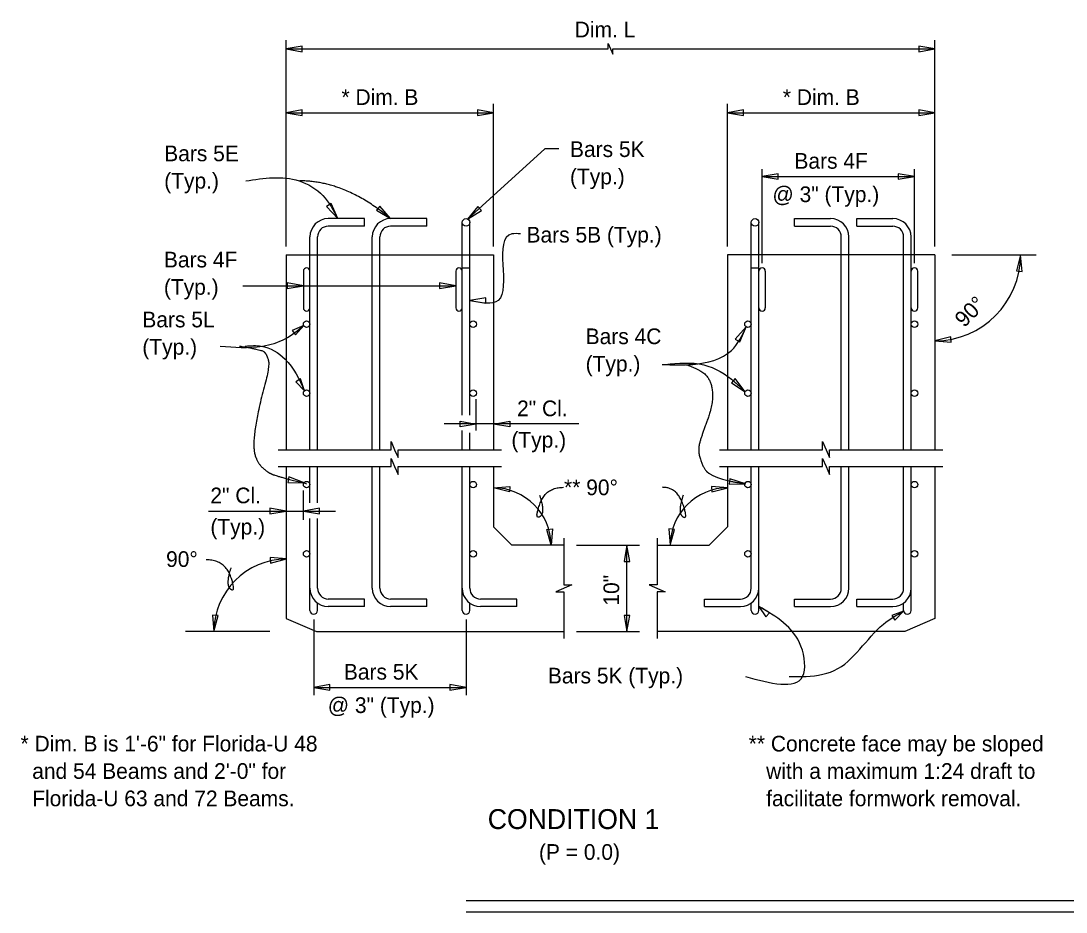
# Model space of a CAD drawing. Extents: x 120790.7 to 120844.8, y 120612.1 to 120653.6.
# Drawn here: x 120791.21 to 120801.28, y 120612.48 to 120621.08 of the extents above; entities that cross this region are included whole.
import ezdxf

# ---------------------------------------------------------------- set-up
doc = ezdxf.new("R2010")
doc.units = 0
for name, color, linetype in [('AdhocPoint_dp', 7, 'Continuous'), ('Patterning', 7, 'Continuous'), ('PlotBorder_dp', 7, 'Continuous'), ('SheetBorder_dp', 7, 'Continuous')]:
    doc.layers.add(name, color=color, linetype=linetype)

# ---------------------------------------------------------------- blocks, each defined once
blk = doc.blocks.new('Terminator-Arrow')
at = {"layer": 'PlotBorder_dp'}
blk.add_lwpolyline([(0, 0), (-0.00041, 0.000069), (-0.00041, -0.000069)], close=True, dxfattribs=at)

msp = doc.modelspace()

# ---------------------------------------------------------------- linework, layer by layer
at = {"layer": 'AdhocPoint_dp'}
for p, q in [((120793.762, 120618.823), (120795.762, 120618.823)), ((120793.762, 120618.823), (120793.762, 120616.945)), ((120795.762, 120618.823), (120795.762, 120616.945)), ((120800.017, 120618.823), (120798.017, 120618.823)), ((120798.017, 120618.823), (120798.017, 120616.945)), ((120800.017, 120618.823), (120800.017, 120616.945)), ((120793.762, 120616.783), (120793.762, 120615.316)), ((120795.762, 120616.783), (120795.762, 120616.201)), ((120798.017, 120616.783), (120798.017, 120616.201)), ((120800.017, 120616.783), (120800.017, 120615.316)), ((120795.939, 120616.024), (120795.762, 120616.201)), ((120797.841, 120616.024), (120798.017, 120616.201)), ((120796.44, 120616.024), (120795.939, 120616.024)), ((120797.34, 120616.024), (120797.841, 120616.024)), ((120793.762, 120615.316), (120794.054, 120615.191)), ((120800.017, 120615.316), (120799.726, 120615.191)), ((120794.054, 120615.191), (120796.44, 120615.191)), ((120799.726, 120615.191), (120797.34, 120615.191))]:
    msp.add_line(p, q, dxfattribs=at)
at = {"layer": 'PlotBorder_dp'}
for p, q in [((120793.762, 120618.906), (120793.762, 120620.896)), ((120793.762, 120618.906), (120793.762, 120620.896)), ((120800.017, 120618.906), (120800.017, 120620.896)), ((120800.017, 120618.906), (120800.017, 120620.896)), ((120793.762, 120620.195), (120795.762, 120620.195)), ((120793.762, 120620.195), (120795.762, 120620.195)), ((120795.762, 120618.906), (120795.762, 120620.28)), ((120795.762, 120618.906), (120795.762, 120620.28)), ((120798.017, 120618.906), (120798.017, 120620.28)), ((120798.017, 120618.906), (120798.017, 120620.28)), ((120798.017, 120620.195), (120800.017, 120620.195)), ((120798.017, 120620.195), (120800.017, 120620.195)), ((120798.351, 120618.744), (120798.351, 120619.651)), ((120798.351, 120618.744), (120798.351, 120619.651)), ((120798.351, 120619.58), (120799.82, 120619.58)), ((120798.351, 120619.58), (120799.82, 120619.58)), ((120799.82, 120618.744), (120799.82, 120619.651)), ((120799.82, 120618.744), (120799.82, 120619.651)), ((120800.18, 120618.823), (120800.994, 120618.823)), ((120800.18, 120618.823), (120800.994, 120618.823)), ((120793.344, 120618.527), (120793.929, 120618.527)), ((120793.344, 120618.527), (120793.929, 120618.527)), ((120793.929, 120618.527), (120795.398, 120618.527)), ((120793.929, 120618.527), (120795.398, 120618.527)), ((120795.596, 120617.13), (120795.596, 120617.431)), ((120795.596, 120617.13), (120795.596, 120617.431)), ((120796.585, 120617.193), (120795.286, 120617.193)), ((120796.585, 120617.193), (120795.286, 120617.193)), ((120793.929, 120616.268), (120793.929, 120616.551)), ((120793.929, 120616.268), (120793.929, 120616.551)), ((120793.013, 120616.353), (120794.239, 120616.353)), ((120793.013, 120616.353), (120794.239, 120616.353)), ((120796.561, 120616.024), (120797.169, 120616.024)), ((120796.561, 120616.024), (120797.169, 120616.024)), ((120797.048, 120615.191), (120797.048, 120616.024)), ((120797.048, 120615.191), (120797.048, 120616.024)), ((120794.028, 120615.308), (120794.028, 120614.577)), ((120794.028, 120615.308), (120794.028, 120614.577)), ((120795.497, 120615.308), (120795.497, 120614.577)), ((120795.497, 120615.308), (120795.497, 120614.577)), ((120793.605, 120615.191), (120792.791, 120615.191)), ((120793.605, 120615.191), (120792.791, 120615.191)), ((120796.561, 120615.191), (120797.169, 120615.191)), ((120796.561, 120615.191), (120797.169, 120615.191)), ((120794.028, 120614.652), (120795.497, 120614.652)), ((120794.028, 120614.652), (120795.497, 120614.652)), ((120802.747, 120612.593), (120795.497, 120612.593)), ((120802.747, 120612.593), (120795.497, 120612.593)), ((120802.747, 120612.485), (120795.497, 120612.485)), ((120802.747, 120612.485), (120795.497, 120612.485))]:
    msp.add_line(p, q, dxfattribs=at)
for points in [[(120793.762, 120620.81), (120796.867, 120620.81), (120796.867, 120620.862), (120796.89, 120620.81), (120796.912, 120620.759), (120796.912, 120620.81), (120800.017, 120620.81)], [(120793.762, 120620.81), (120796.867, 120620.81), (120796.867, 120620.862), (120796.89, 120620.81), (120796.912, 120620.759), (120796.912, 120620.81), (120800.017, 120620.81)], [(120796.39, 120619.846), (120796.257, 120619.846), (120795.512, 120619.167)], [(120796.39, 120619.846), (120796.257, 120619.846), (120795.512, 120619.167)], [(120793.687, 120616.945), (120794.775, 120616.945), (120794.775, 120617.023), (120794.808, 120616.945), (120794.842, 120616.868), (120794.842, 120616.945), (120795.838, 120616.945)], [(120793.687, 120616.945), (120794.775, 120616.945), (120794.775, 120617.023), (120794.808, 120616.945), (120794.842, 120616.868), (120794.842, 120616.945), (120795.838, 120616.945)], [(120797.942, 120616.945), (120798.935, 120616.945), (120798.935, 120617.023), (120798.968, 120616.945), (120799.002, 120616.868), (120799.002, 120616.945), (120800.093, 120616.945)], [(120797.942, 120616.945), (120798.935, 120616.945), (120798.935, 120617.023), (120798.968, 120616.945), (120799.002, 120616.868), (120799.002, 120616.945), (120800.093, 120616.945)], [(120793.687, 120616.783), (120794.775, 120616.783), (120794.775, 120616.861), (120794.808, 120616.783), (120794.842, 120616.706), (120794.842, 120616.783), (120795.838, 120616.783)], [(120793.687, 120616.783), (120794.775, 120616.783), (120794.775, 120616.861), (120794.808, 120616.783), (120794.842, 120616.706), (120794.842, 120616.783), (120795.838, 120616.783)], [(120797.942, 120616.783), (120798.935, 120616.783), (120798.935, 120616.861), (120798.968, 120616.783), (120799.002, 120616.706), (120799.002, 120616.783), (120800.093, 120616.783)], [(120797.942, 120616.783), (120798.935, 120616.783), (120798.935, 120616.861), (120798.968, 120616.783), (120799.002, 120616.706), (120799.002, 120616.783), (120800.093, 120616.783)], [(120796.44, 120616.092), (120796.44, 120615.642), (120796.517, 120615.642), (120796.362, 120615.574), (120796.44, 120615.574), (120796.44, 120615.124)], [(120796.44, 120616.092), (120796.44, 120615.642), (120796.517, 120615.642), (120796.362, 120615.574), (120796.44, 120615.574), (120796.44, 120615.124)], [(120797.34, 120616.092), (120797.34, 120615.642), (120797.263, 120615.642), (120797.418, 120615.574), (120797.34, 120615.574), (120797.34, 120615.124)], [(120797.34, 120616.092), (120797.34, 120615.642), (120797.263, 120615.642), (120797.418, 120615.574), (120797.34, 120615.574), (120797.34, 120615.124)]]:
    msp.add_lwpolyline(points, dxfattribs=at)
for points in [[(120794.26, 120619.174), (120794.198, 120619.32), (120794.153, 120619.291)], [(120794.26, 120619.174), (120794.198, 120619.32), (120794.153, 120619.291)], [(120794.77, 120619.174), (120794.667, 120619.295), (120794.633, 120619.254)], [(120794.77, 120619.174), (120794.667, 120619.295), (120794.633, 120619.254)], [(120795.512, 120619.167), (120795.645, 120619.253), (120795.61, 120619.292)], [(120795.512, 120619.167), (120795.645, 120619.253), (120795.61, 120619.292)], [(120800.843, 120618.823), (120800.805, 120618.669), (120800.857, 120618.665)], [(120800.843, 120618.823), (120800.805, 120618.669), (120800.857, 120618.665)], [(120793.929, 120618.527), (120793.773, 120618.553), (120793.773, 120618.5)], [(120793.929, 120618.527), (120793.773, 120618.553), (120793.773, 120618.5)], [(120795.398, 120618.527), (120795.242, 120618.553), (120795.242, 120618.5)], [(120795.398, 120618.527), (120795.242, 120618.553), (120795.242, 120618.5)], [(120795.533, 120618.384), (120795.689, 120618.357), (120795.689, 120618.41)], [(120795.533, 120618.384), (120795.689, 120618.357), (120795.689, 120618.41)], [(120793.932, 120618.143), (120793.822, 120618.096), (120793.852, 120618.053)], [(120793.932, 120618.143), (120793.822, 120618.096), (120793.852, 120618.053)], [(120798.199, 120618.13), (120798.093, 120618.012), (120798.138, 120617.984)], [(120798.199, 120618.13), (120798.093, 120618.012), (120798.138, 120617.984)], [(120800.017, 120617.995), (120800.175, 120617.982), (120800.171, 120618.035)], [(120800.017, 120617.995), (120800.175, 120617.982), (120800.171, 120618.035)], [(120793.941, 120617.514), (120793.902, 120617.628), (120793.857, 120617.6)], [(120793.941, 120617.514), (120793.902, 120617.628), (120793.857, 120617.6)], [(120798.187, 120617.503), (120798.092, 120617.63), (120798.056, 120617.591)], [(120798.187, 120617.503), (120798.092, 120617.63), (120798.056, 120617.591)], [(120793.937, 120616.624), (120793.79, 120616.682), (120793.779, 120616.63)], [(120793.937, 120616.624), (120793.79, 120616.682), (120793.779, 120616.63)], [(120798.191, 120616.617), (120798.04, 120616.664), (120798.033, 120616.612)], [(120798.191, 120616.617), (120798.04, 120616.664), (120798.033, 120616.612)], [(120795.762, 120616.578), (120795.92, 120616.591), (120795.916, 120616.538)], [(120795.762, 120616.578), (120795.92, 120616.591), (120795.916, 120616.538)], [(120798.02, 120616.578), (120797.862, 120616.591), (120797.866, 120616.538)], [(120798.02, 120616.578), (120797.862, 120616.591), (120797.866, 120616.538)], [(120796.317, 120616.023), (120796.276, 120616.175), (120796.329, 120616.181)], [(120796.317, 120616.023), (120796.276, 120616.175), (120796.329, 120616.181)], [(120797.465, 120616.023), (120797.506, 120616.175), (120797.453, 120616.181)], [(120797.465, 120616.023), (120797.506, 120616.175), (120797.453, 120616.181)], [(120797.048, 120616.024), (120797.022, 120615.868), (120797.075, 120615.868)], [(120797.048, 120616.024), (120797.022, 120615.868), (120797.075, 120615.868)], [(120793.765, 120615.891), (120793.607, 120615.904), (120793.611, 120615.851)], [(120793.765, 120615.891), (120793.607, 120615.904), (120793.611, 120615.851)], [(120793.065, 120615.191), (120793.106, 120615.344), (120793.054, 120615.349)], [(120793.065, 120615.191), (120793.106, 120615.344), (120793.054, 120615.349)], [(120797.048, 120615.191), (120797.075, 120615.347), (120797.022, 120615.347)], [(120797.048, 120615.191), (120797.075, 120615.347), (120797.022, 120615.347)], [(120798.32, 120615.434), (120798.386, 120615.334), (120798.423, 120615.372)], [(120798.32, 120615.434), (120798.386, 120615.334), (120798.423, 120615.372)], [(120799.716, 120615.388), (120799.603, 120615.346), (120799.632, 120615.302)], [(120799.716, 120615.388), (120799.603, 120615.346), (120799.632, 120615.302)]]:
    msp.add_lwpolyline(points, close=True, dxfattribs=at)
for centre, radius, start, end in [((120800.015, 120618.823), 0.828, 270.1769, 0), ((120800.015, 120618.823), 0.828, 270.1769, 0), ((120795.758, 120616.019), 0.559, 0.3991, 89.55), ((120795.758, 120616.019), 0.559, 0.3991, 89.55), ((120798.024, 120616.019), 0.559, 90.45, 179.6009), ((120798.024, 120616.019), 0.559, 90.45, 179.6009), ((120793.77, 120615.186), 0.705, 90.45, 179.6009), ((120793.77, 120615.186), 0.705, 90.45, 179.6009)]:
    msp.add_arc(centre, radius, start, end, dxfattribs=at)
for points in [[(120793.373, 120619.538), (120793.887, 120619.538), (120794.117, 120619.396), (120794.26, 120619.174)], [(120793.373, 120619.538), (120793.887, 120619.538), (120794.117, 120619.396), (120794.26, 120619.174)], [(120796.023, 120619.026), (120795.939, 120619.026), (120795.807, 120618.384), (120795.533, 120618.384)], [(120796.023, 120619.026), (120795.939, 120619.026), (120795.807, 120618.384), (120795.533, 120618.384)], [(120793.125, 120617.944), (120793.534, 120617.944), (120793.753, 120618.015), (120793.932, 120618.143)], [(120793.125, 120617.944), (120793.534, 120617.944), (120793.753, 120618.015), (120793.932, 120618.143)], [(120797.389, 120617.768), (120797.683, 120617.768), (120798.056, 120617.902), (120798.199, 120618.13)], [(120797.389, 120617.768), (120797.683, 120617.768), (120798.056, 120617.902), (120798.199, 120618.13)], [(120793.369, 120617.944), (120793.523, 120617.944), (120793.753, 120617.818), (120793.941, 120617.514)], [(120793.369, 120617.944), (120793.523, 120617.944), (120793.753, 120617.818), (120793.941, 120617.514)], [(120797.417, 120617.768), (120797.788, 120617.763), (120798.089, 120617.597), (120798.187, 120617.503)], [(120797.417, 120617.768), (120797.788, 120617.763), (120798.089, 120617.597), (120798.187, 120617.503)], [(120798.19, 120614.757), (120798.741, 120614.757), (120798.726, 120615.049), (120798.32, 120615.434)], [(120798.19, 120614.757), (120798.741, 120614.757), (120798.726, 120615.049), (120798.32, 120615.434)], [(120798.611, 120614.757), (120798.735, 120614.757), (120799.047, 120614.815), (120799.522, 120615.262), (120799.716, 120615.388)], [(120798.611, 120614.757), (120798.735, 120614.757), (120799.047, 120614.815), (120799.522, 120615.262), (120799.716, 120615.388)]]:
    msp.add_spline(points, degree=3, dxfattribs=at)
for points in [[(120794.77, 120619.174), (120794.332, 120619.538), (120793.895, 120619.538)], [(120794.77, 120619.174), (120794.332, 120619.538), (120793.895, 120619.538)], [(120793.313, 120617.944), (120793.528, 120617.911), (120793.574, 120617.865), (120793.608, 120617.753), (120793.49, 120617.328), (120793.438, 120616.966), (120793.49, 120616.811), (120793.593, 120616.718), (120793.707, 120616.681), (120793.958, 120616.617)], [(120793.313, 120617.944), (120793.528, 120617.911), (120793.574, 120617.865), (120793.608, 120617.753), (120793.49, 120617.328), (120793.438, 120616.966), (120793.49, 120616.811), (120793.593, 120616.718), (120793.707, 120616.681), (120793.958, 120616.617)], [(120797.617, 120617.765), (120797.783, 120617.712), (120797.874, 120617.569), (120797.874, 120617.365), (120797.778, 120617.108), (120797.726, 120616.937), (120797.788, 120616.761), (120797.85, 120616.704), (120798.011, 120616.642), (120798.191, 120616.617)], [(120797.617, 120617.765), (120797.783, 120617.712), (120797.874, 120617.569), (120797.874, 120617.365), (120797.778, 120617.108), (120797.726, 120616.937), (120797.788, 120616.761), (120797.85, 120616.704), (120798.011, 120616.642), (120798.191, 120616.617)], [(120796.206, 120616.505), (120796.264, 120616.333), (120796.153, 120616.264), (120796.265, 120616.582), (120796.437, 120616.582)], [(120796.206, 120616.505), (120796.264, 120616.333), (120796.153, 120616.264), (120796.265, 120616.582), (120796.437, 120616.582)], [(120797.59, 120616.505), (120797.532, 120616.333), (120797.643, 120616.264), (120797.53, 120616.582), (120797.391, 120616.582)], [(120797.59, 120616.505), (120797.532, 120616.333), (120797.643, 120616.264), (120797.53, 120616.582), (120797.391, 120616.582)], [(120793.23, 120615.806), (120793.173, 120615.634), (120793.284, 120615.565), (120793.171, 120615.882), (120792.993, 120615.882)], [(120793.23, 120615.806), (120793.173, 120615.634), (120793.284, 120615.565), (120793.171, 120615.882), (120792.993, 120615.882)]]:
    msp.add_open_spline(points, degree=2, dxfattribs=at)
at = {"layer": 'SheetBorder_dp'}
for p, q in [((120794.517, 120619.174), (120794.169, 120619.174)), ((120794.517, 120619.101), (120794.169, 120619.101)), ((120794.517, 120619.101), (120794.517, 120619.174)), ((120795.118, 120619.174), (120794.77, 120619.174)), ((120795.118, 120619.101), (120794.77, 120619.101)), ((120795.118, 120619.101), (120795.118, 120619.174)), ((120795.46, 120617.278), (120795.46, 120619.137)), ((120795.533, 120617.278), (120795.533, 120619.137)), ((120798.247, 120616.945), (120798.247, 120619.137)), ((120798.32, 120616.945), (120798.32, 120619.137)), ((120798.663, 120619.174), (120799.011, 120619.174)), ((120798.663, 120619.101), (120798.663, 120619.174)), ((120798.663, 120619.101), (120799.011, 120619.101)), ((120799.263, 120619.174), (120799.611, 120619.174)), ((120799.263, 120619.101), (120799.263, 120619.174)), ((120799.263, 120619.101), (120799.611, 120619.101)), ((120793.992, 120616.945), (120793.992, 120618.997)), ((120794.065, 120616.945), (120794.065, 120618.997)), ((120794.593, 120616.945), (120794.593, 120618.997)), ((120794.665, 120616.945), (120794.665, 120618.997)), ((120799.115, 120616.945), (120799.115, 120618.997)), ((120799.188, 120616.945), (120799.188, 120618.997)), ((120799.715, 120616.945), (120799.715, 120618.997)), ((120799.788, 120616.945), (120799.788, 120618.997)), ((120795.46, 120618.698), (120795.533, 120618.698)), ((120798.247, 120618.698), (120798.32, 120618.698)), ((120793.929, 120618.667), (120793.929, 120618.313)), ((120795.398, 120618.667), (120795.398, 120618.313)), ((120798.382, 120618.667), (120798.382, 120618.313)), ((120799.851, 120618.667), (120799.851, 120618.313)), ((120795.46, 120616.945), (120795.46, 120617.131)), ((120795.533, 120616.945), (120795.533, 120617.109)), ((120793.992, 120616.432), (120793.992, 120616.783)), ((120794.065, 120616.432), (120794.065, 120616.783)), ((120794.593, 120615.608), (120794.593, 120616.783)), ((120794.665, 120615.608), (120794.665, 120616.783)), ((120795.46, 120615.394), (120795.46, 120616.783)), ((120795.533, 120615.608), (120795.533, 120616.783)), ((120798.247, 120615.608), (120798.247, 120616.783)), ((120798.32, 120615.394), (120798.32, 120616.783)), ((120799.115, 120615.608), (120799.115, 120616.783)), ((120799.188, 120615.608), (120799.188, 120616.783)), ((120799.715, 120615.608), (120799.715, 120616.783)), ((120799.788, 120615.394), (120799.788, 120616.783)), ((120793.992, 120615.394), (120793.992, 120616.28)), ((120794.065, 120615.608), (120794.065, 120616.28)), ((120794.065, 120615.394), (120794.065, 120615.465)), ((120794.517, 120615.504), (120794.169, 120615.504)), ((120794.517, 120615.431), (120794.517, 120615.504)), ((120795.118, 120615.504), (120794.77, 120615.504)), ((120795.118, 120615.431), (120795.118, 120615.504)), ((120795.533, 120615.394), (120795.533, 120615.465)), ((120795.985, 120615.504), (120795.637, 120615.504)), ((120795.985, 120615.431), (120795.985, 120615.504)), ((120797.795, 120615.504), (120798.142, 120615.504)), ((120797.795, 120615.431), (120797.795, 120615.504)), ((120798.247, 120615.394), (120798.247, 120615.465)), ((120798.663, 120615.504), (120799.011, 120615.504)), ((120798.663, 120615.431), (120798.663, 120615.504)), ((120799.263, 120615.504), (120799.611, 120615.504)), ((120799.263, 120615.431), (120799.263, 120615.504)), ((120799.715, 120615.394), (120799.715, 120615.465)), ((120794.517, 120615.431), (120794.169, 120615.431)), ((120795.118, 120615.431), (120794.77, 120615.431)), ((120795.985, 120615.431), (120795.637, 120615.431)), ((120797.795, 120615.431), (120798.142, 120615.431)), ((120798.663, 120615.431), (120799.011, 120615.431)), ((120799.263, 120615.431), (120799.611, 120615.431))]:
    msp.add_line(p, q, dxfattribs=at)
for centre, radius in [((120795.497, 120619.137), 0.0365), ((120798.283, 120619.137), 0.0365), ((120793.96, 120618.156), 0.0312), ((120795.565, 120618.156), 0.0312), ((120798.215, 120618.156), 0.0312), ((120799.82, 120618.156), 0.0312), ((120793.96, 120617.49), 0.0312), ((120795.565, 120617.49), 0.0312), ((120798.215, 120617.49), 0.0312), ((120799.82, 120617.49), 0.0312), ((120793.96, 120616.608), 0.0312), ((120795.565, 120616.608), 0.0312), ((120798.215, 120616.608), 0.0312), ((120799.82, 120616.608), 0.0312), ((120793.96, 120615.941), 0.0312), ((120795.565, 120615.941), 0.0312), ((120798.215, 120615.941), 0.0312), ((120799.82, 120615.941), 0.0312)]:
    msp.add_circle(centre, radius, dxfattribs=at)
for centre, radius, start, end in [((120794.169, 120618.997), 0.177, 90, 180), ((120794.169, 120618.997), 0.104, 90, 180), ((120794.77, 120618.997), 0.177, 90, 180), ((120794.77, 120618.997), 0.104, 90, 180), ((120799.011, 120618.997), 0.177, 0, 90), ((120799.011, 120618.997), 0.104, 0, 90), ((120799.611, 120618.997), 0.177, 0, 90), ((120799.611, 120618.997), 0.104, 0, 90), ((120793.96, 120618.667), 0.0312, 0, 180), ((120795.429, 120618.667), 0.0312, 0, 180), ((120798.351, 120618.667), 0.0312, 0, 180), ((120799.82, 120618.667), 0.0312, 0, 180), ((120793.96, 120618.313), 0.0312, 180, 0), ((120795.429, 120618.313), 0.0312, 180, 0), ((120798.351, 120618.313), 0.0312, 180, 0), ((120799.82, 120618.313), 0.0312, 180, 0), ((120794.169, 120615.608), 0.177, 180, 270), ((120794.169, 120615.608), 0.104, 180, 270), ((120794.77, 120615.608), 0.177, 180, 270), ((120794.77, 120615.608), 0.104, 180, 270), ((120795.637, 120615.608), 0.177, 180, 270), ((120795.637, 120615.608), 0.104, 180, 270), ((120798.142, 120615.608), 0.104, 270, 360), ((120798.142, 120615.608), 0.177, 270, 360), ((120799.011, 120615.608), 0.104, 270, 0), ((120799.011, 120615.608), 0.177, 270, 0), ((120799.611, 120615.608), 0.104, 270, 360), ((120799.611, 120615.608), 0.177, 270, 360), ((120794.028, 120615.394), 0.0365, 180, 0), ((120795.497, 120615.394), 0.0365, 180, 0), ((120798.283, 120615.394), 0.0365, 180, 0), ((120799.752, 120615.394), 0.0365, 180, 0)]:
    msp.add_arc(centre, radius, start, end, dxfattribs=at)

# ---------------------------------------------------------------- block references
at = {"layer": 'PlotBorder_dp', "xscale": 381, "rotation": 180}
for p, yscale in [((120793.762, 120620.81), 384.0238095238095), ((120793.762, 120620.81), 384.0238095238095), ((120793.762, 120620.195), 384.0238095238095), ((120793.762, 120620.195), 384.0238095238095), ((120798.017, 120620.195), 384.0238095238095), ((120798.017, 120620.195), 384.0238095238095), ((120798.351, 120619.58), 384.0238095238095), ((120798.351, 120619.58), 384.0238095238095), ((120795.762, 120617.192), -384.0238095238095), ((120795.762, 120617.192), -384.0238095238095), ((120793.929, 120616.353), 384.0238095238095), ((120793.929, 120616.353), 384.0238095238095), ((120794.028, 120614.652), 384.0238095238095), ((120794.028, 120614.652), 384.0238095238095)]:
    msp.add_blockref('Terminator-Arrow', p, dxfattribs=dict(at, yscale=yscale))
at = {"layer": 'PlotBorder_dp', "xscale": 381}
for p, yscale in [((120800.017, 120620.81), 384.0238095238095), ((120800.017, 120620.81), 384.0238095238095), ((120795.762, 120620.195), 384.0238095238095), ((120795.762, 120620.195), 384.0238095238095), ((120800.017, 120620.195), 384.0238095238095), ((120800.017, 120620.195), 384.0238095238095), ((120799.819, 120619.58), 384.0238095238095), ((120799.819, 120619.58), 384.0238095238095), ((120795.596, 120617.192), -384.0238095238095), ((120795.596, 120617.192), -384.0238095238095), ((120793.762, 120616.353), 384.0238095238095), ((120793.762, 120616.353), 384.0238095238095), ((120795.497, 120614.652), 384.0238095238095), ((120795.497, 120614.652), 384.0238095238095)]:
    msp.add_blockref('Terminator-Arrow', p, dxfattribs=dict(at, yscale=yscale))

# ---------------------------------------------------------------- texts
at = {"layer": 'Patterning'}
for s, height, p in [('Dim. L', 0.1512, (120796.545, 120620.922)), ('* Dim. B', 0.1512, (120794.296, 120620.27)), ('* Dim. B', 0.1512, (120798.551, 120620.27)), ('Bars 4F', 0.1512, (120798.663, 120619.655)), ('@ 3" (Typ.)', 0.1512, (120798.451, 120619.333)), ('Bars 5B (Typ.)', 0.1512, (120796.08, 120618.943)), ('2" Cl.', 0.1512, (120795.989, 120617.268)), ('(Typ.)', 0.1512, (120795.934, 120616.965)), ('** 90°', 0.1512, (120796.442, 120616.506)), ('2" Cl.', 0.1512, (120793.032, 120616.428)), ('(Typ.)', 0.1512, (120793.032, 120616.126)), ('90°', 0.1512, (120792.605, 120615.814)), ('Bars 5K', 0.1512, (120794.319, 120614.727)), ('Bars 5K (Typ.)', 0.1512, (120796.286, 120614.69)), ('@ 3" (Typ.)', 0.1512, (120794.164, 120614.405)), ('CONDITION 1', 0.192, (120795.706, 120613.286)), ('(P = 0.0)', 0.1512, (120796.2, 120612.989))]:
    msp.add_text(s, height=height, dxfattribs=at).set_placement(p)
for s, rotation, p in [(' 90°', 45, (120800.26, 120618.077)), ('10"', 90, (120796.973, 120615.441))]:
    msp.add_text(s, height=0.1512, rotation=rotation, dxfattribs=at).set_placement(p)
at = {"layer": 'PlotBorder_dp'}
for s, p in [('Bars 5K', (120796.499, 120619.768)), ('Bars 5E', (120792.587, 120619.727)), ('(Typ.)', (120792.587, 120619.463)), ('(Typ.)', (120796.499, 120619.504)), ('Bars 4F', (120792.584, 120618.703)), ('(Typ.)', (120792.584, 120618.439)), ('Bars 5L', (120792.376, 120618.125)), ('Bars 4C', (120796.65, 120617.963)), ('(Typ.)', (120792.376, 120617.861)), ('(Typ.)', (120796.65, 120617.699)), ('* Dim. B is 1\'-6" for Florida-U 48', (120791.202, 120614.034)), ('** Concrete face may be sloped', (120798.222, 120614.034)), ('  and 54 Beams and 2\'-0" for ', (120791.202, 120613.77)), ('   with a maximum 1:24 draft to', (120798.222, 120613.77)), ('  Florida-U 63 and 72 Beams.', (120791.202, 120613.506)), ('   facilitate formwork removal.', (120798.222, 120613.506))]:
    msp.add_text(s, height=0.1512, dxfattribs=at).set_placement(p)

doc.saveas('drawing.dxf')
